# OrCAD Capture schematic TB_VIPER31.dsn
size C
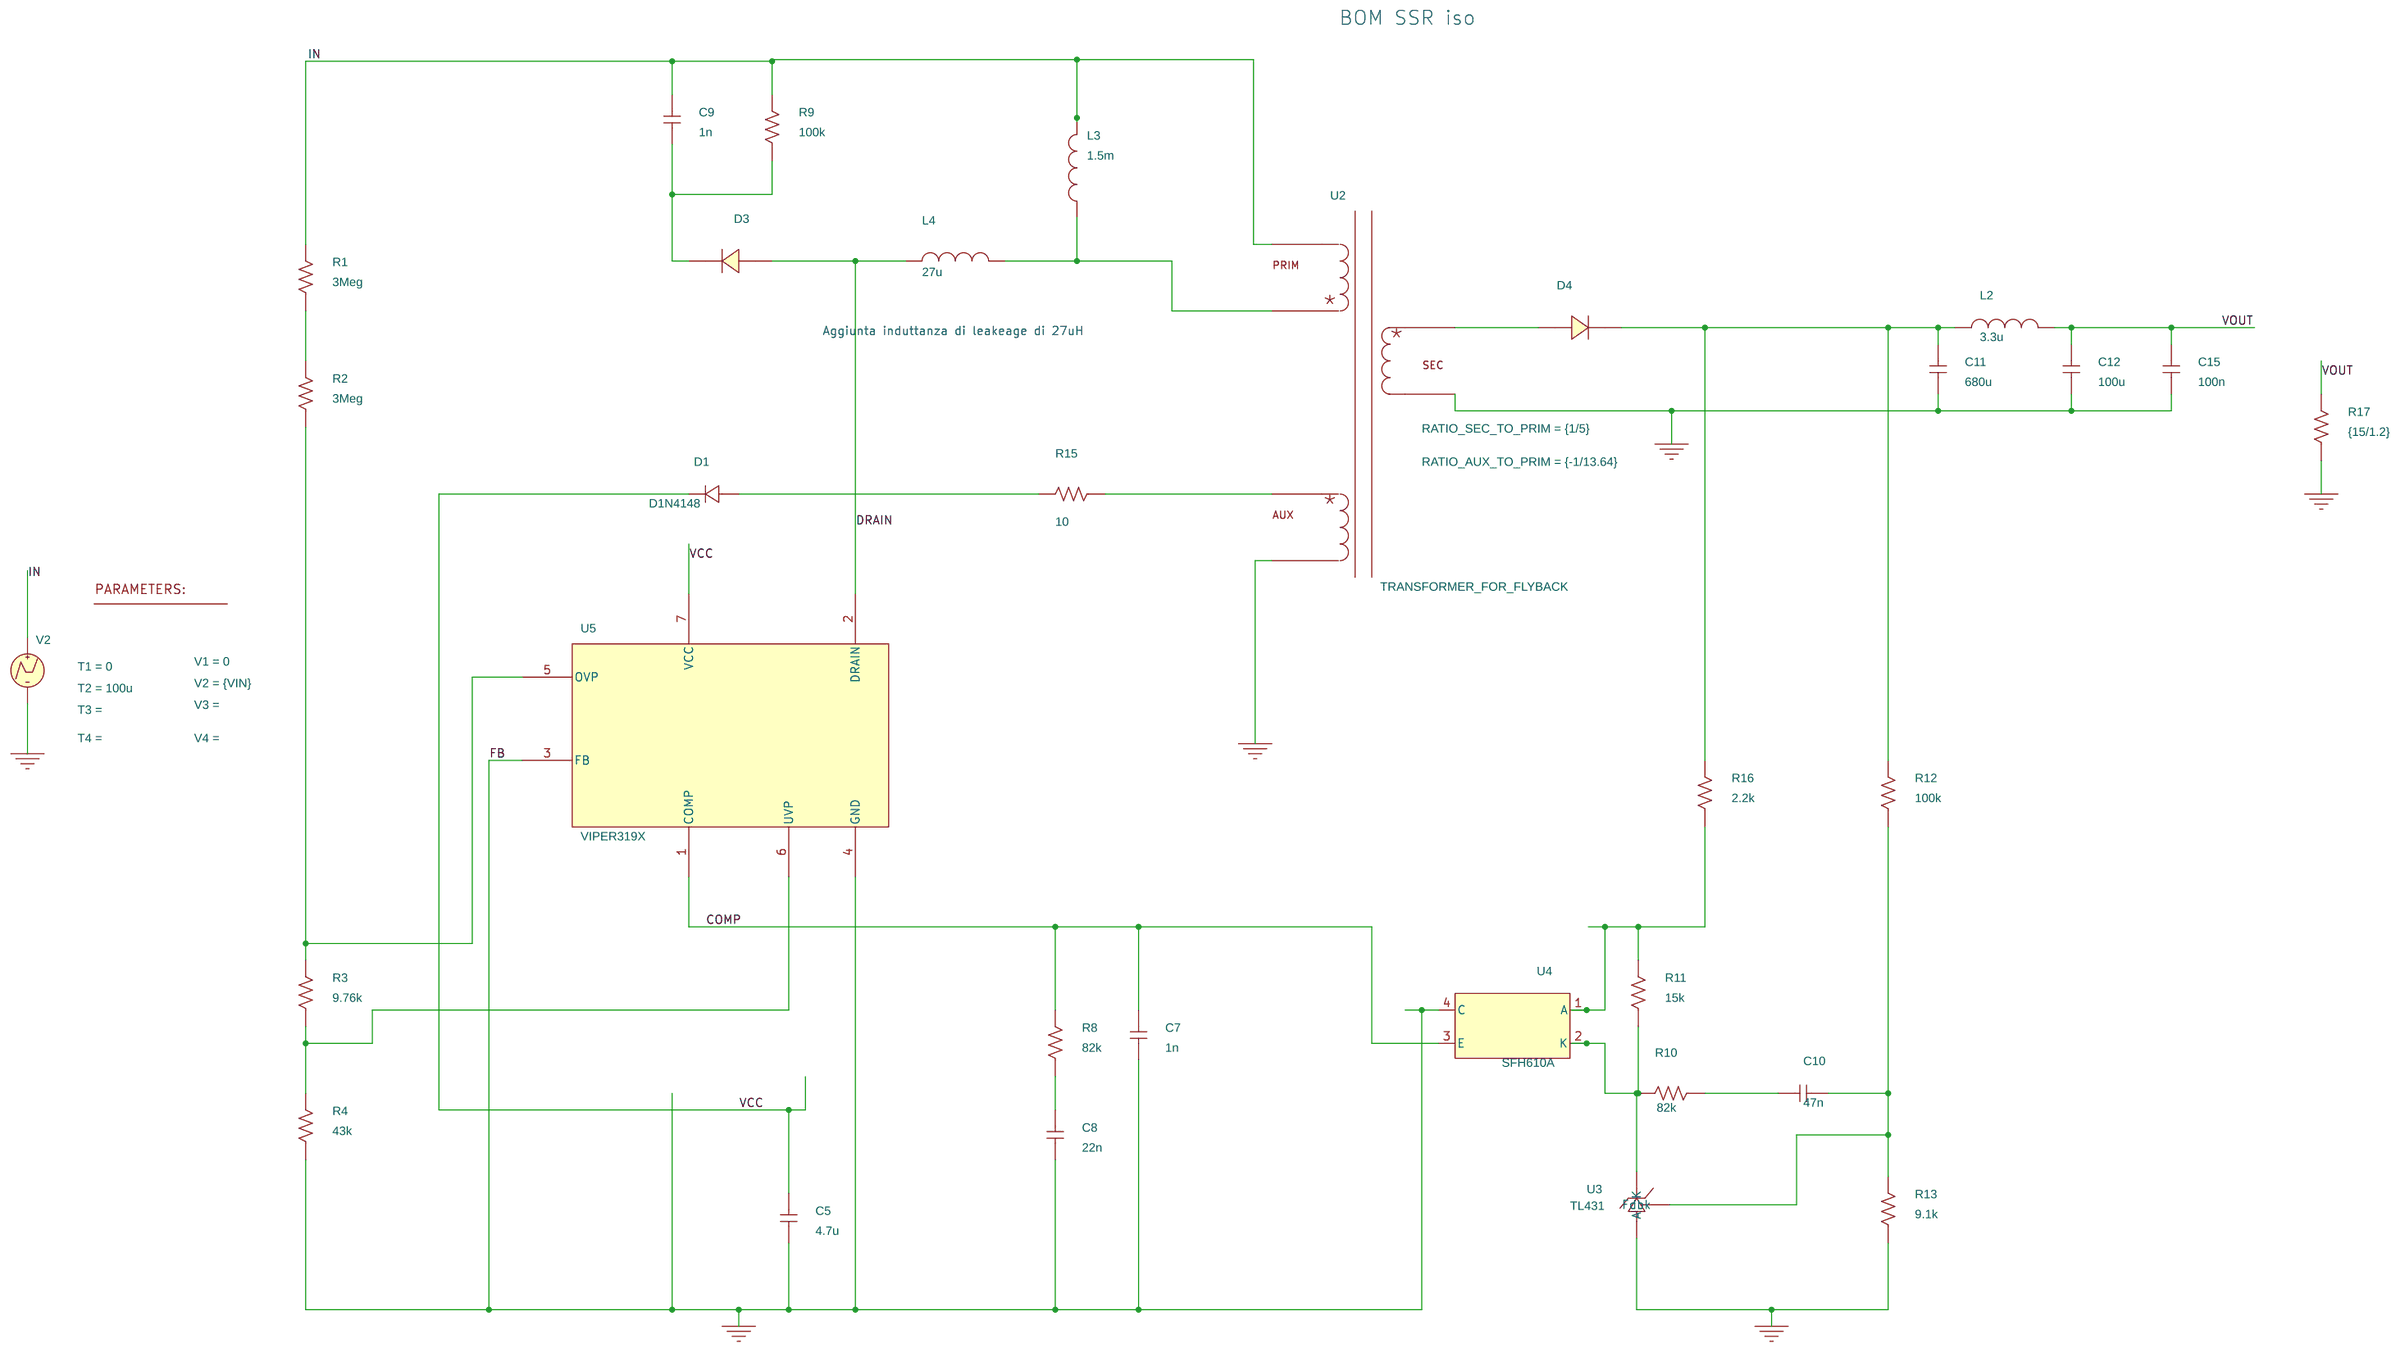
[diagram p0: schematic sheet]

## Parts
2  PARAM
C5  4.7u  [RAD/CK05]
C7  1n  [RAD/CK05]
C8  22n  [RAD/CK05]
C9  1n  [RAD/CK05]
C10  47n  [RAD/CK05]
C11  680u  [RAD/CK05]
C12  100u  [RAD/CK05]
C15  100n  [RAD/CK05]
D1  D1N4148  [dax2do35]
D3  STPS3150U  [SMB]
D4  STPS3150U  [SMB]
L2  3.3u  [L2012C]
L3  1.5m  [L2012C]
L4  27u  [L2012C]
R1  3Meg  [RC05]
R2  3Meg  [RC05]
R3  9.76k  [RC05]
R4  43k  [RC05]
R8  82k  [RC05]
R9  100k  [RC05]
R10  82k  [RC05]
R11  15k  [RC05]
R12  100k  [RC05]
R13  9.1k  [RC05]
R15  10  [RC05]
R16  2.2k  [RC05]
R17  {15/1.2}  [RC05]
U2  TRANSFORMER_FOR_FLYBACK
U3  TL431
U4  SFH610A
U5  VIPER319X
V2  VPWL

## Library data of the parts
2 = PARAM: VIN: 220
C5 C7-C12 C15 = C
D1 = D1N4148
D3 D4 = STPS3150U
L2-L4 = L
R1-R4 R8-R13 R15-R17 = R
U2 = TRANSFORMER_FOR_FLYBACK: RATIO_AUX_TO_PRIM: {-1/13.64}; RATIO_SEC_TO_PRIM: {1/5}
U3 = TLV431
U4 = SFH610A
U5 = VIPER319X
V2 = VPWL: T1: 0; T2: 100u; V1: 0; V2: {VIN}

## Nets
VCC: C5.2 D1.2 U5.7(VCC)
0: C5.1 C7.1 C8.1 C11.1 C12.1 C15.1 R4.1 R13.1 R17.1 U2.4 U2.11 U3.A U4.4(C) U5.3(FB) U5.4(GND) V2.2(-)
COMP: C7.2 R8.2 U4.3(E) U5.1(COMP)
DRAIN: D3.2(A) L4.1 U5.2(DRAIN)
IN: C9.2 L3.2 R1.2 R9.2 U2.1 V2.1(+)
VOUT: C12.2 C15.2 L2.2 R17.2
N5128001: R1.1 R2.2
N5128009: R2.1 R3.2 U5.5(OVP)
N5128013: R3.1 R4.2 U5.6(UVP)
N5128293: C8.2 R8.1
N5967874: D1.1 R15.2
N5968073: C9.1 D3.1(C) R9.1
N5968329: R15.1 U2.3
N5968848: R11.2 R16.1 U4.1(A)
N5968978: C10.2 R12.1 R13.2 U3.Fdbk
N5969209: L3.1 L4.2 U2.2
N5969240: D4.2(A) U2.10
N5969310: C11.2 D4.1(C) L2.1 R12.2 R16.2
N5972710: C10.1 R10.1
N5973419: R10.2 R11.1 U3.K U4.2(K)

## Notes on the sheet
- BOM SSR iso
- Aggiunta induttanza di leakeage di 27uH
